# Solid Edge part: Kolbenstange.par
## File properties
Username: bmolnar
Dokumentum tartalom típus: 0
Author: bmolnar
Last saved by: bmolnar
Revision: 93
Sűrűség: 0,000 kg/m^3
Pontosság: 0,990
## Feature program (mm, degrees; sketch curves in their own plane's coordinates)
base feature "unnamed BaseFeature 1"
sketch for "unnamed Protrusion 1" plane through (67.2, 0, 0) normal (1, 0, 0) x-axis (0, 0, 1)
  circle centre (0, 0) radius 50
extrude "unnamed Protrusion 1" add finite 23.3 along +normal
sketch for "Kihúzás_2" plane through (67.2, 0, 0) normal (1, 0, 0) x-axis (0, 0, 1)
  circle centre (0, 0) radius 50
extrude "Kihúzás_2" add finite 4.7 along -normal
thread "unnamed Thread 1"
chamfer "Letörés_1" setback 3.3  SetBackValue2 = 20 deg
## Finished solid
Body 1: solid body, 17 faces, 23 edges, 8 vertices.
  Faces by surface: plane 8, cylinder 4, torus 3, cone 2
  Edges by curve: circle 13, line 6, ellipse 2, intersection 2
Bounding box of the edges (mm; curved faces can reach further): 285.500 x 100.000 x 100.000, from (-195, -50, -50) to (90.5, 50, 50).
Cylindrical faces by radius (mm): R7 x1, R8 x1, R12.5 x1, R50 x1
Conical faces (half-angle, radius in mm at the cone's reference point): 20 deg R6.7989 x1, 60 deg R7.6 x1
Toroidal faces (ring radius, tube radius in mm): R7.4 r0.4 x2, R10.7 r1.8 x1
Planar faces by outward normal: +x 1, +z 1, -x 3, -z 1, oblique 2
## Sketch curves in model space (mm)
circle centre (67.2, 0, 0) radius 50
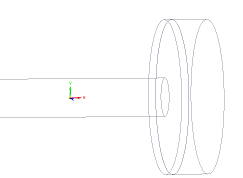
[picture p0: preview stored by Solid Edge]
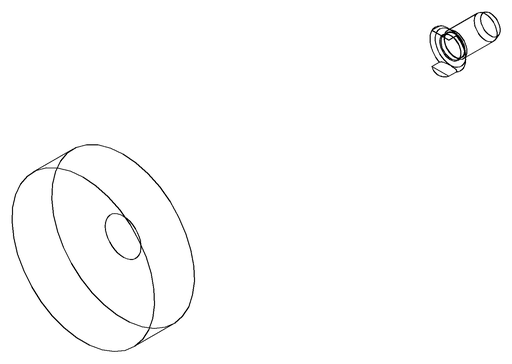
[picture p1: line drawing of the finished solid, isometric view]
